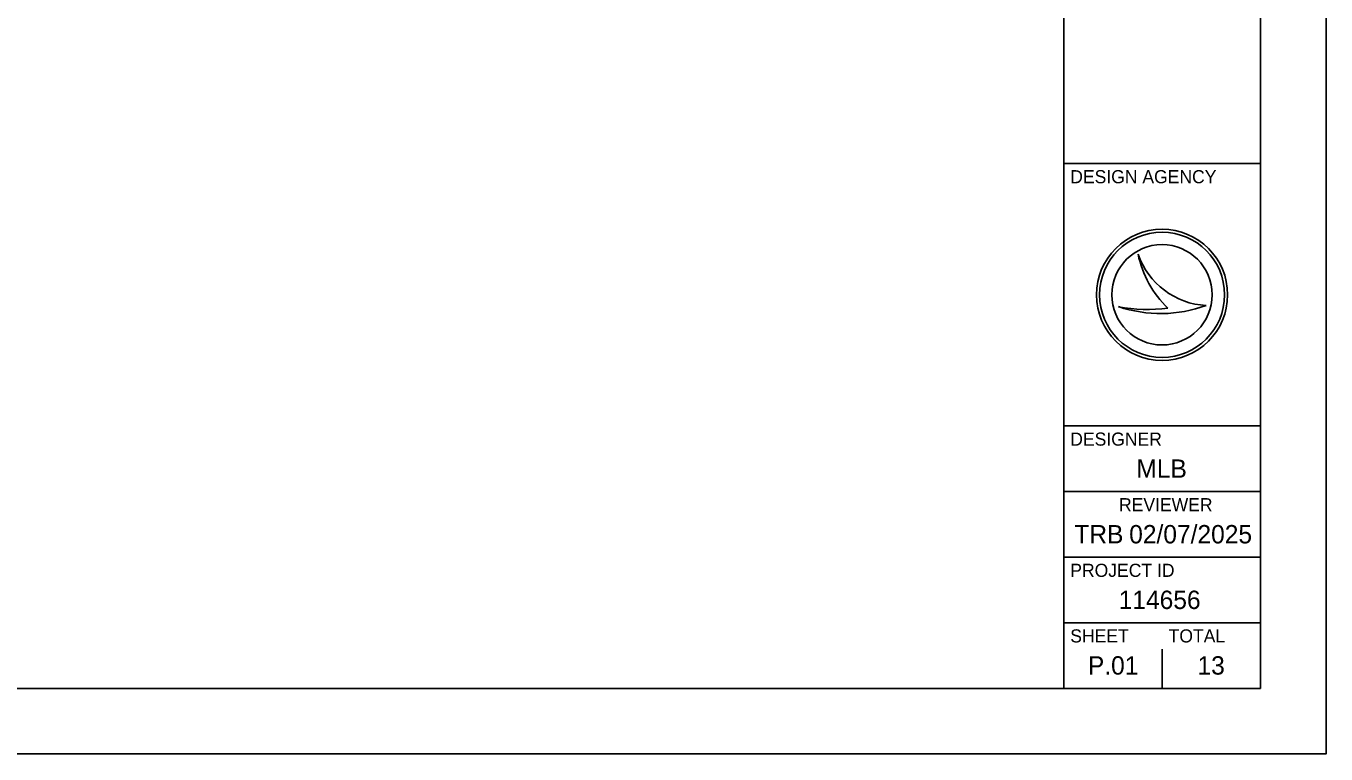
# Model space of a CAD drawing. Extents: x 0 to 44.3, y 0 to 22.
# Drawn here: x 24.09 to 34, y 0 to 5.55 of the extents above; entities that cross this region are included whole.
import ezdxf

# ---------------------------------------------------------------- set-up
doc = ezdxf.new("R2010")
doc.units = 0
for name, color, linetype in [('SH_Border', 7, 'Continuous'), ('SH_Cut_Line', 7, 'Continuous'), ('SH_Data', 7, 'Continuous')]:
    doc.layers.add(name, color=color, linetype=linetype)

msp = doc.modelspace()

# ---------------------------------------------------------------- linework, layer by layer
at = {"layer": 'SH_Border'}
for p, q in [((32, 0.5), (32, 21.5)), ((32, 4.5), (33.5, 4.5)), ((32, 2.5), (33.5, 2.5)), ((32, 2), (33.5, 2)), ((32, 1.5), (33.5, 1.5)), ((32, 1), (33.5, 1))]:
    msp.add_line(p, q, dxfattribs=at)
msp.add_lwpolyline([(1.5, 21.5), (33.5, 21.5), (33.5, 0.5), (1.5, 0.5)], close=True, dxfattribs=at)
at = {"layer": 'SH_Cut_Line'}
msp.add_lwpolyline([(0, 0), (34, 0), (34, 22), (0, 22)], close=True, dxfattribs=at)
at = {"layer": 'SH_Data'}
for p, q in [((32.5674, 3.8096), (32.5675, 3.8096)), ((32.75, 3.5), (32.75, 3.5)), ((32.4172, 3.4095), (32.4172, 3.4095)), ((33.0873, 3.4185), (33.0873, 3.4185)), ((32.75, 0.5), (32.75, 0.8)), ((32.375, 0.675), (32.375, 0.675))]:
    msp.add_line(p, q, dxfattribs=at)
for radius in [0.5, 0.4768, 0.4768, 0.3822]:
    msp.add_circle((32.75, 3.5), radius, dxfattribs=at)
for centre, radius, start, end in [((33.1159, 3.9976), 0.5798, 198.92567, 198.93195), ((33.3467, 3.9701), 0.7956, 191.63793, 191.64215), ((33.1159, 3.9976), 0.5798, 198.93195, 267.16574), ((33.3467, 3.9701), 0.7956, 191.64215, 226.09467), ((32.7394, 4.37), 1.0131, 251.45764, 290.08324), ((32.648, 4.6543), 1.2661, 259.49639, 259.49952), ((32.7394, 4.37), 1.0131, 251.45274, 251.45764), ((32.648, 4.6543), 1.2661, 259.49952, 276.66723)]:
    msp.add_arc(centre, radius, start, end, dxfattribs=at)

# ---------------------------------------------------------------- texts
for s, height, p in [('DESIGN AGENCY', 0.1, (32.05, 4.35)), ('DESIGNER', 0.1, (32.05, 2.35)), ('MLB', 0.14, (32.5541, 2.105)), ('REVIEWER', 0.1, (32.4218, 1.85)), ('TRB', 0.14, (32.0811, 1.605)), ('02/07/2025', 0.14, (32.4993, 1.605)), ('PROJECT ID', 0.1, (32.05, 1.35)), ('114656', 0.14, (32.4191, 1.105)), ('SHEET', 0.1, (32.05, 0.85)), ('TOTAL', 0.1, (32.8, 0.85)), ('P.01', 0.14, (32.1844, 0.605)), ('13', 0.14, (33.02, 0.605))]:
    msp.add_text(s, height=height, dxfattribs=at).set_placement(p)

doc.saveas('drawing.dxf')
